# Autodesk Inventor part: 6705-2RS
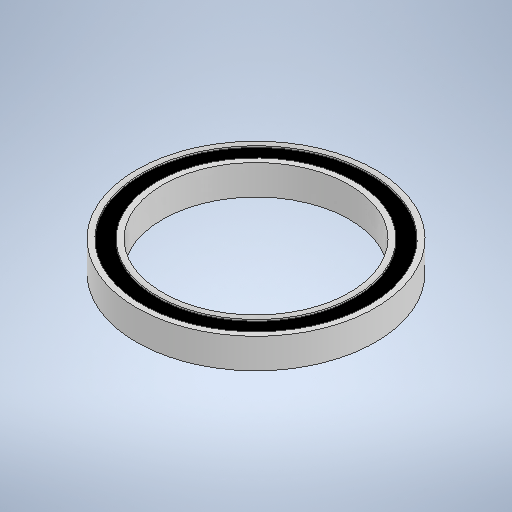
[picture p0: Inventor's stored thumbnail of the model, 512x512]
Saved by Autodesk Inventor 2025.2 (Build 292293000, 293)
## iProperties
Created: 2025-06
Part Number: 6705-2RS
Material: Generico
Document SubType Name: Modeling
Designer: R5800u
Density: 1 g/cm^3
Appearance: Default
Author: R5800u
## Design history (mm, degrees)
sketch "Schizzo1"
  geometry: C1 r 12.5 at (0, 0); C2 r 16 at (0, 0); 1 further point
  constraints: 2 centre point, 2 coincident
  dimensions: "d0" = 25 diameter of C1; "d1" = 32 diameter of C2
extrude "Estrusione1" new body sketch "Schizzo1" stored distance "d2" = 4; taper "d3" = 0 deg
sketch "Schizzo2"
  geometry: C1 r 13.25 at (0, 0); C2 r 15.25 at (0, 0); 1 further point
  constraints: 2 centre point, 2 coincident
  dimensions: "d4" = 26.5 diameter of C1; "d5" = 30.5 diameter of C2
extrude "Estrusione2" cut sketch "Schizzo2" distance "d6" = 0.2; taper "d7" = 0 deg
mirror "Speculare1"
node "Solido1"
